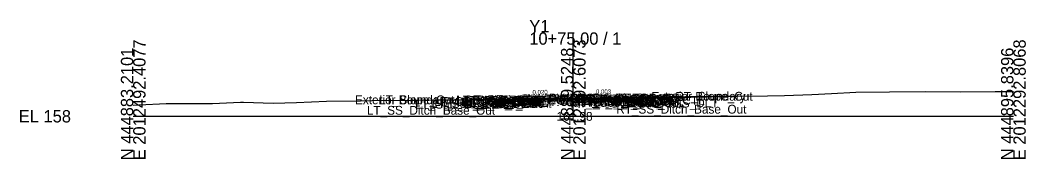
# Model space of a CAD drawing. Extents: x -26 to 3203, y -10 to 9517.
# Drawn here: x -25.7 to 202.8, y 1490.3 to 1521.9 of the extents above; entities that cross this region are included whole.
import ezdxf

# ---------------------------------------------------------------- set-up
doc = ezdxf.new("R2010")
doc.units = 0
for name, color, linetype in [('Default', 7, 'Continuous'), ('Exist CMT Pavement', 7, 'Continuous'), ('Exist Cross Section Cell', 7, 'Continuous'), ('Exist XS Center Line Elevation Label', 7, 'Continuous'), ('Exist XS Ground Line', 7, 'Continuous'), ('Prop CMT Pvmt Course 1', 7, 'Continuous'), ('Prop CMT Pvmt Course 1 Wedge', 7, 'Continuous'), ('Prop CMT Pvmt Course 2', 7, 'Continuous'), ('Prop CMT Pvmt Course 2 Wedge', 7, 'Continuous'), ('Prop CMT Pvmt Course 3', 7, 'Continuous'), ('Prop CMT Pvmt Course 3 Wedge', 7, 'Continuous'), ('Prop CMT Pvmt Surface', 7, 'Continuous'), ('Prop CMT Pvmt Surface Shoulder', 7, 'Continuous'), ('Prop CMT Pvmt Wedge Surface 1', 7, 'Continuous'), ('Prop CMT Pvmt Wedge Surface 2', 7, 'Continuous'), ('Prop CMT Pvmt Wedge Surface 3', 7, 'Continuous'), ('Prop CMT Shld Paved Course 1', 7, 'Continuous'), ('Prop CMT Shld Paved Course 2', 7, 'Continuous'), ('Prop CMT Shld Paved Course 3', 7, 'Continuous'), ('Prop CMT Slope Grass', 7, 'Continuous'), ('Prop CMT Subgrade Earthwork', 7, 'Continuous'), ('Prop XS Earthwork Shape', 7, 'Continuous'), ('Prop XS SE Text', 7, 'Continuous'), ('Prop XS Wedging', 7, 'Continuous'), ('Scratch_Level_0', 7, 'Continuous')]:
    doc.layers.add(name, color=color, linetype=linetype)

msp = doc.modelspace()

# ---------------------------------------------------------------- linework, layer by layer
at = {"layer": 'Exist CMT Pavement'}
for points in [[(86.03, 1503.7), (86.51, 1503.66), (94.07, 1503.9), (97.96, 1504), (100, 1503.98)], [(100, 1503.98), (107.99, 1503.92), (109.96, 1503.89), (111.82, 1504.16)]]:
    msp.add_lwpolyline(points, dxfattribs=at)
at = {"layer": 'Exist Cross Section Cell'}
for p, q in [((100, 1500), (100, 1519.08)), ((0, 1500), (100, 1500)), ((100, 1500), (200, 1500))]:
    msp.add_line(p, q, dxfattribs=at)
at = {"layer": 'Exist XS Ground Line'}
msp.add_lwpolyline([(0, 1502.54), (1.39, 1502.57), (7.46, 1502.87), (18, 1502.94), (24.35, 1503.21), (25.1, 1503.21), (31.82, 1503), (37.1, 1503.14), (43.93, 1503.42), (51.68, 1503.54), (54.19, 1503.59), (63.32, 1503.66), (64.81, 1503.67), (73.89, 1503.71), (74.51, 1503.71), (75.05, 1503.71), (85.39, 1503.79), (86.09, 1503.69), (86.51, 1503.66), (94.07, 1503.9), (97.96, 1504), (100, 1503.98), (107.99, 1503.92), (109.96, 1503.89), (111.82, 1504.16), (113.26, 1504.21), (117.01, 1504.29), (124.1, 1504.35), (126.57, 1504.46), (134.12, 1504.52), (137.27, 1504.55), (144.14, 1504.65), (147.97, 1504.74), (154.17, 1504.92), (158.67, 1505.15), (164.19, 1505.51), (171.87, 1505.58), (180.06, 1505.64), (187.9, 1505.59), (195.84, 1505.63), (197.33, 1505.63), (200, 1505.63)], dxfattribs=at)
at = {"layer": 'Prop CMT Pvmt Course 1'}
for points in [[(100, 1504.14), (85.03, 1503.84)], [(85.03, 1503.84), (85.03, 1503.59)], [(86.03, 1503.73), (100, 1504.01)], [(100, 1503.89), (100, 1504.14)], [(100, 1504.14), (113.73, 1504.09)], [(100, 1503.89), (100, 1504.14)], [(100, 1504.01), (100, 1503.89), (100, 1503.89)], [(111.82, 1503.97), (100, 1504.01)], [(100, 1504.01), (100, 1503.89), (100, 1503.89)], [(111.82, 1503.85), (111.82, 1503.97)], [(113.73, 1503.84), (111.82, 1503.85)], [(113.73, 1504.09), (113.73, 1503.84)], [(85.03, 1503.59), (86.03, 1503.61)], [(86.03, 1503.61), (86.03, 1503.73)]]:
    msp.add_lwpolyline(points, dxfattribs=at)
at = {"layer": 'Prop CMT Pvmt Course 1 Wedge'}
for points in [[(100, 1504.01), (86.03, 1503.73)], [(100, 1504.01), (111.82, 1503.97)]]:
    msp.add_lwpolyline(points, dxfattribs=at)
at = {"layer": 'Prop CMT Pvmt Course 2'}
for points in [[(111.82, 1503.52), (111.82, 1503.85)], [(111.82, 1503.85), (113.73, 1503.84)], [(113.73, 1503.84), (113.73, 1503.51)], [(86.03, 1503.61), (85.03, 1503.59)], [(85.03, 1503.59), (85.03, 1503.26)], [(85.03, 1503.26), (86.03, 1503.28)], [(86.03, 1503.28), (86.03, 1503.61)], [(113.73, 1503.51), (111.82, 1503.52)]]:
    msp.add_lwpolyline(points, dxfattribs=at)
at = {"layer": 'Prop CMT Pvmt Course 2 Wedge'}
for points in [[(100, 1503.89), (86.03, 1503.61)], [(100, 1503.89), (111.82, 1503.85)]]:
    msp.add_lwpolyline(points, dxfattribs=at)
at = {"layer": 'Prop CMT Pvmt Course 3'}
for points in [[(86.03, 1503.28), (85.03, 1503.26)], [(85.03, 1503.26), (85.03, 1502.92)], [(85.03, 1502.92), (86.03, 1502.94)], [(86.03, 1502.94), (86.03, 1503.28)], [(111.82, 1503.52), (113.73, 1503.51)], [(111.82, 1503.18), (111.82, 1503.52)], [(113.73, 1503.18), (111.82, 1503.18)], [(113.73, 1503.51), (113.73, 1503.18)]]:
    msp.add_lwpolyline(points, dxfattribs=at)
at = {"layer": 'Prop CMT Pvmt Course 3 Wedge'}
for points in [[(100, 1503.55), (86.03, 1503.28)], [(100, 1503.55), (111.82, 1503.52)]]:
    msp.add_lwpolyline(points, dxfattribs=at)
at = {"layer": 'Prop CMT Pvmt Surface'}
for points in [[(100, 1504.14), (85.03, 1503.84)], [(100, 1504.14), (113.73, 1504.09)]]:
    msp.add_lwpolyline(points, dxfattribs=at)
at = {"layer": 'Prop CMT Pvmt Surface Shoulder'}
for points in [[(85.03, 1503.84), (85.03, 1503.84)], [(113.73, 1504.09), (113.73, 1504.09)]]:
    msp.add_lwpolyline(points, dxfattribs=at)
at = {"layer": 'Prop CMT Pvmt Wedge Surface 1'}
for points in [[(85.03, 1503.59), (85.03, 1503.84)], [(100, 1504.01), (86.03, 1503.73)], [(100, 1504.01), (111.82, 1503.97)], [(111.82, 1503.97), (111.82, 1503.85)], [(111.82, 1503.85), (113.73, 1503.84)], [(113.73, 1503.84), (113.73, 1504.09)], [(86.03, 1503.61), (85.03, 1503.59)], [(86.03, 1503.73), (86.03, 1503.61)]]:
    msp.add_lwpolyline(points, dxfattribs=at)
at = {"layer": 'Prop CMT Pvmt Wedge Surface 2'}
for points in [[(100, 1503.89), (85.03, 1503.59)], [(85.03, 1503.59), (85.03, 1503.84)], [(100, 1503.89), (113.73, 1503.84)], [(113.73, 1503.84), (113.73, 1504.09)]]:
    msp.add_lwpolyline(points, dxfattribs=at)
at = {"layer": 'Prop CMT Pvmt Wedge Surface 3'}
for points in [[(85.03, 1503.26), (85.03, 1503.84)], [(113.73, 1503.51), (113.73, 1504.09)], [(100, 1503.55), (85.03, 1503.26)], [(100, 1503.55), (113.73, 1503.51)]]:
    msp.add_lwpolyline(points, dxfattribs=at)
at = {"layer": 'Prop CMT Shld Paved Course 1'}
for points in [[(85.03, 1503.84), (84.77, 1503.58)], [(85.03, 1503.84), (85.03, 1503.84)], [(85.03, 1503.59), (85.03, 1503.84)], [(113.73, 1504.09), (113.73, 1504.09)], [(113.73, 1504.09), (113.98, 1503.84)], [(113.73, 1503.84), (113.73, 1504.09)], [(113.98, 1503.84), (113.73, 1503.84)], [(84.77, 1503.58), (85.03, 1503.59)]]:
    msp.add_lwpolyline(points, dxfattribs=at)
at = {"layer": 'Prop CMT Shld Paved Course 2'}
for points in [[(113.73, 1503.84), (113.98, 1503.84), (114.32, 1503.5)], [(113.73, 1503.51), (113.73, 1503.84)], [(85.03, 1503.59), (84.77, 1503.58), (84.43, 1503.24)], [(84.43, 1503.24), (85.03, 1503.26)], [(85.03, 1503.26), (85.03, 1503.59)], [(114.32, 1503.5), (113.73, 1503.51)]]:
    msp.add_lwpolyline(points, dxfattribs=at)
at = {"layer": 'Prop CMT Shld Paved Course 3'}
for points in [[(85.03, 1503.26), (84.43, 1503.24), (83.93, 1503.23), (83.59, 1502.89)], [(83.59, 1502.89), (85.03, 1502.92)], [(85.03, 1502.92), (85.03, 1503.26)], [(113.73, 1503.51), (114.32, 1503.5), (114.82, 1503.49), (115.16, 1503.15)], [(113.73, 1503.18), (113.73, 1503.51)], [(115.16, 1503.15), (113.73, 1503.18)]]:
    msp.add_lwpolyline(points, dxfattribs=at)
at = {"layer": 'Prop CMT Slope Grass'}
msp.add_line((85.03, 1503.84), (72.14, 1503.7), dxfattribs=at)
msp.add_lwpolyline([(113.73, 1504.09), (137.27, 1504.55)], dxfattribs=at)
at = {"layer": 'Prop CMT Subgrade Earthwork'}
for p, q in [((83.59, 1502.89), (82.67, 1503.81)), ((116.16, 1504.14), (115.16, 1503.15))]:
    msp.add_line(p, q, dxfattribs=at)
for points in [[(111.82, 1503.18), (111.82, 1504.16)], [(85.03, 1502.92), (83.59, 1502.89)], [(86.03, 1502.94), (85.03, 1502.92)], [(86.03, 1502.94), (86.03, 1503.7)], [(111.82, 1503.18), (113.73, 1503.18)], [(113.73, 1503.18), (115.16, 1503.15)]]:
    msp.add_lwpolyline(points, dxfattribs=at)
at = {"layer": 'Prop XS Earthwork Shape'}
for points in [[(72.14, 1503.7), (82.67, 1503.81), (82.72, 1503.77)], [(82.72, 1503.77), (83.59, 1502.89), (86.03, 1502.94), (86.03, 1503.7), (85.39, 1503.79)], [(111.39, 1504.1), (111.82, 1504.1), (111.82, 1503.18), (115.16, 1503.15), (116.16, 1504.14), (137.27, 1504.55), (134.12, 1504.52), (126.57, 1504.46), (124.1, 1504.35), (117.01, 1504.29), (113.26, 1504.21), (111.82, 1504.16)], [(86.03, 1503.7), (86.09, 1503.69), (86.51, 1503.66)]]:
    msp.add_lwpolyline(points, close=True, dxfattribs=at)
at = {"layer": 'Prop XS Wedging'}
for p, q in [((93.6, 1503.89), (86.03, 1503.73)), ((86.51, 1503.66), (93.6, 1503.89)), ((100, 1504.01), (98.81, 1503.99)), ((98.81, 1503.99), (100, 1503.98)), ((100, 1503.98), (100, 1504.01)), ((110.54, 1503.98), (100, 1504.01)), ((100, 1504.01), (100, 1503.98)), ((100, 1503.98), (100, 1503.98)), ((100, 1503.98), (107.99, 1503.92)), ((107.99, 1503.92), (109.96, 1503.89)), ((109.96, 1503.89), (110.54, 1503.98)), ((86.03, 1503.73), (86.03, 1503.7)), ((86.03, 1503.7), (86.51, 1503.66))]:
    msp.add_line(p, q, dxfattribs=at)
msp.add_lwpolyline([(86.03, 1503.7), (86.03, 1503.7)], dxfattribs=at)

# ---------------------------------------------------------------- texts
at = {"layer": 'Default'}
msp.add_text('-', height=0.0001, dxfattribs=at).set_placement((0, 1500))
at = {"layer": 'Exist Cross Section Cell'}
for s, p in [('Y1', (90, 1519.08)), ('10+75.00 / 1', (90, 1516.28)), ('EL 158', (-26, 1498.6))]:
    msp.add_text(s, height=2.8, dxfattribs=at).set_placement(p)
for s, p in [('N 444883.2101', (0, 1490)), ('E 2012492.4077', (2.8, 1490)), ('N 444889.5248', (100, 1490)), ('E 2012392.6073', (102.8, 1490)), ('N 444895.8396', (200, 1490)), ('E 2012292.8068', (202.8, 1490))]:
    msp.add_text(s, height=2.8, rotation=90, dxfattribs=at).set_placement(p)
at = {"layer": 'Exist XS Center Line Elevation Label'}
msp.add_text('161.98', height=2, dxfattribs=at).set_placement((96.2, 1498.98))
at = {"layer": 'Prop XS SE Text'}
for s, rotation, p in [('0.020', 1.1458, (90.74, 1504.95)), ('0.003', 359.8162, (105.14, 1505.12))]:
    msp.add_text(s, height=1, rotation=rotation, dxfattribs=at).set_placement(p)
at = {"layer": 'Scratch_Level_0'}
for s, p in [('Exterior Boundary', (50.41, 1502.74)), ('LT_Slope_Cut', (55.9, 1502.74)), ('LT_Sub_OSS_DLT', (64.01, 1501.75)), ('LT_Sub_Trench_Out', (67.79, 1501.89)), ('LT_GS_OS_CTL', (68.4, 1502.36)), ('LT_PS3_Shelf_Out', (69.91, 1502.23)), ('LT_Sub Tie Out', (73.37, 1502.7)), ('LT_PV_OEEOP_EG', (73.57, 1502.7)), ('LT_PS3_OEOP', (74.67, 1502.24)), ('LT_PS2_OEOP', (75.01, 1502.58)), ('LT_Sub_OEOT', (75.1, 1501.92)), ('LT_PV2_OEOT', (75.2, 1502.59)), ('LT_PV3_OEOT', (75.2, 1502.26)), ('LT_Sub_OEEOP', (75.24, 1501.94)), ('LT_PV2_OEEOP', (75.33, 1502.61)), ('LT_PV3_OEEOP', (75.33, 1502.28)), ('LT_PV1_OEOT', (75.77, 1502.84)), ('LT_PS1_OEOP', (75.83, 1502.84)), ('LT_PV1_OEEOP', (75.9, 1502.73)), ('RT_PV_IEEOP_EG', (88.14, 1502.98)), ('LT_PV_IEEOP_EG', (88.19, 1502.98)), ('RT_PV2_IEEOP', (89.91, 1502.89)), ('RT_PV3_IEEOP', (89.91, 1502.55)), ('LT_PV2_IEEOP', (89.95, 1502.89)), ('LT_PV3_IEEOP', (89.95, 1502.55)), ('RT_PV1_IEEOP', (90.47, 1503.01)), ('LT_PV1_IEEOP', (90.52, 1503.01)), ('PV2_PGL', (93.91, 1502.89)), ('PV1_PGL', (94.47, 1503.14)), ('RT_Sub Tie Out', (99.11, 1503.16)), ('RT_PV_OEEOP_EG', (99.31, 1503.16)), ('RT_Sub_Trench_Out', (99.32, 1502.15)), ('RT_PS3_Shelf_Out', (100.76, 1502.49)), ('RT_Sub_OEEOP', (100.98, 1502.18)), ('RT_PV2_OEEOP', (101.08, 1502.85)), ('RT_PV3_OEEOP', (101.08, 1502.52)), ('RT_PV1_OEEOP', (101.65, 1502.97)), ('RT_Sub_OEOT', (103.76, 1502.18)), ('RT_PV2_OEOT', (103.85, 1502.84)), ('RT_PV3_OEOT', (103.85, 1502.51)), ('RT_PS2_OEOP', (104.17, 1502.84)), ('RT_PV1_OEOT', (104.42, 1503.09)), ('RT_PS1_OEOP', (104.48, 1503.09)), ('RT_PS3_OEOP', (104.51, 1502.5)), ('RT_GS_OS_CTL', (109.05, 1502.61)), ('RT_Sub_OSS_DLT', (109.5, 1502.01)), ('Exterior Boundary', (117.75, 1503.55)), ('RT_Slope_Cut', (123.2, 1503.55)), ('LT_SS_Ditch_Base_Out', (53.1, 1500.36)), ('RT_SS_Ditch_Base_Out', (109.76, 1500.61))]:
    msp.add_text(s, height=2, dxfattribs=at).set_placement(p)

doc.saveas('drawing.dxf')
